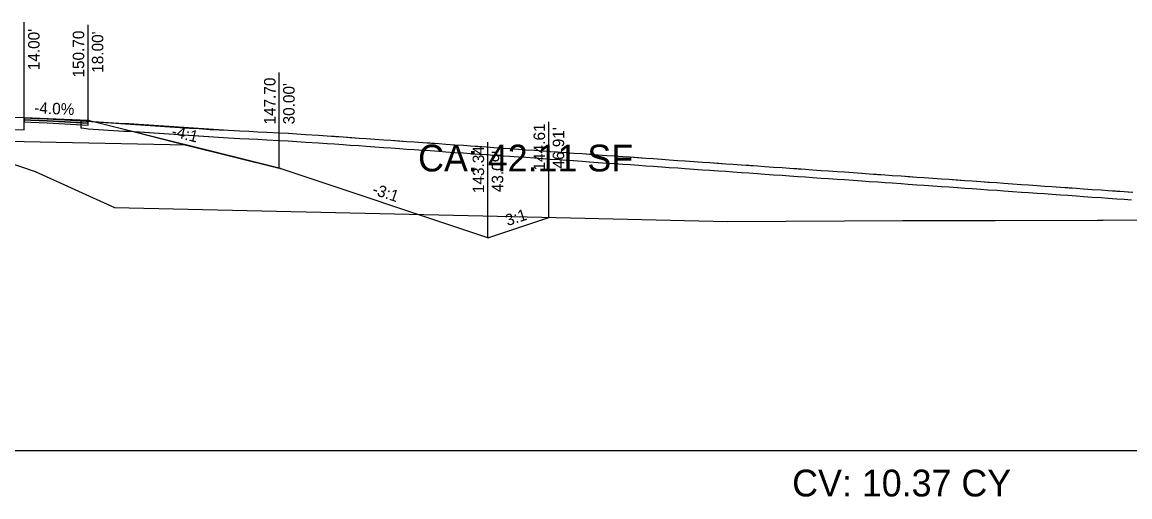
# Model space of a CAD drawing. Extents: x -26 to 4403, y -13 to 9578.
# Drawn here: x 263.9 to 333.4, y 3497.1 to 3526.9 of the extents above; entities that cross this region are included whole.
import ezdxf

# ---------------------------------------------------------------- set-up
doc = ezdxf.new("R2010")
doc.units = 0
for name, color, linetype in [('_CIVIL_CONSTRUCTION', 7, 'Continuous'), ('CONST_DCH', 7, 'Continuous'), ('CONST_LV3', 7, 'Continuous'), ('DTM_CORRIDOR', 7, 'Continuous'), ('DTM_P_FINISHED_GRADE', 7, 'Continuous'), ('DTM_TEMP_DROP', 7, 'Continuous'), ('DTM_X_GROUND', 7, 'Continuous'), ('SLOPE_STAKES_FILL', 7, 'Continuous'), ('XS_CELL', 7, 'Continuous'), ('XS_M_SHAPES_EARTHWORK', 7, 'Continuous'), ('XS_P_ASPHALT', 7, 'Continuous'), ('XS_P_DR_ASPHALT', 7, 'Continuous'), ('XS_P_DR_ASPHALT_B', 7, 'Continuous'), ('XS_P_DR_GRAVEL', 7, 'Continuous'), ('XS_P_GROUND', 7, 'Continuous'), ('XS_P_SHOULDER', 7, 'Continuous'), ('XS_P_SUBGRADE_GRANULAR', 7, 'Continuous'), ('XS_P_TX_CLEARZONE', 7, 'Continuous'), ('XS_P_TX_FS_BS', 7, 'Continuous'), ('XS_SHEET_EW_TX_AREA', 7, 'Continuous'), ('XS_SHEET_EW_TX_VOLUME', 7, 'Continuous')]:
    doc.layers.add(name, color=color, linetype=linetype)

msp = doc.modelspace()

# ---------------------------------------------------------------- linework, layer by layer
at = {"layer": 'CONST_LV3'}
for points in [[(264, 3520.861), (264.203, 3520.853), (264.898, 3520.826), (265.026, 3520.82), (265.203, 3520.813), (265.819, 3520.789), (266.046, 3520.78), (274.373, 3520.208), (274.963, 3520.184), (275.657, 3520.134), (276.23, 3520.111), (276.802, 3520.088), (277.53, 3520.038), (278.089, 3520.016), (278.649, 3519.994), (279.208, 3519.971), (280, 3519.921), (280.55, 3519.899), (281.1, 3519.86), (281.65, 3519.822), (282.453, 3519.776), (283, 3519.737), (283.547, 3519.699), (284, 3519.667), (284.547, 3519.629), (285, 3519.597), (285.453, 3519.566), (286, 3519.527), (286.547, 3519.489), (287, 3519.457), (287.453, 3519.426), (288, 3519.387), (288.453, 3519.356), (289, 3519.317), (289.547, 3519.279), (290, 3519.247), (290.453, 3519.216), (291, 3519.177), (291.547, 3519.139), (292, 3519.107), (292.453, 3519.076), (293, 3519.037), (293.453, 3519.006), (294, 3518.967), (294.453, 3518.936), (295, 3518.897), (295.453, 3518.866), (296, 3518.827), (296.547, 3518.789), (297, 3518.757), (297.453, 3518.726), (298, 3518.687), (298.453, 3518.656), (299, 3518.617), (299.547, 3518.579), (300, 3518.547), (300.547, 3518.509), (301, 3518.477), (301.547, 3518.439), (302, 3518.407), (302.453, 3518.376), (303, 3518.337), (303.453, 3518.306), (304, 3518.267), (304.453, 3518.236), (305, 3518.197), (305.453, 3518.166), (306, 3518.127), (306.547, 3518.089), (307, 3518.057), (307.453, 3518.026), (308, 3517.987), (308.453, 3517.956), (309, 3517.917), (309.547, 3517.879), (310, 3517.847), (310.453, 3517.816), (311, 3517.777), (311.547, 3517.739), (312, 3517.707), (312.453, 3517.676), (313, 3517.637), (313.453, 3517.606), (314, 3517.567), (314.453, 3517.536), (315, 3517.497), (315.453, 3517.466), (316, 3517.427), (316.547, 3517.389), (317, 3517.357), (317.453, 3517.326), (318, 3517.287), (318.453, 3517.256), (319, 3517.217), (319.547, 3517.179), (320, 3517.147), (320.453, 3517.116), (321, 3517.077), (321.547, 3517.039), (322, 3517.007), (322.453, 3516.976), (323, 3516.937), (323.453, 3516.906), (324, 3516.867), (324.547, 3516.829), (325, 3516.797), (325.453, 3516.766), (326, 3516.727), (326.547, 3516.689), (327, 3516.657), (327.547, 3516.619), (328, 3516.587), (328.453, 3516.556), (329, 3516.517), (329.547, 3516.479), (330, 3516.447), (330.453, 3516.416), (331, 3516.377), (331.547, 3516.339), (332, 3516.307), (332.453, 3516.276), (333, 3516.237), (333.547, 3516.199)], [(274.174, 3519.158), (280, 3517.701)]]:
    msp.add_lwpolyline(points, dxfattribs=at)
at = {"layer": 'DTM_P_FINISHED_GRADE'}
for points in [[(264, 3520.861), (264.406, 3520.845), (265.43, 3520.803), (268, 3520.646)], [(267.575, 3520.716), (267.58, 3520.715), (267.583, 3520.715), (267.607, 3520.714), (268, 3520.646), (270.242, 3520.51), (270.562, 3520.497), (276.802, 3520.088), (277.53, 3520.038), (278.089, 3520.016), (278.649, 3519.994), (279.208, 3519.971), (280, 3519.921), (280.55, 3519.899), (281.1, 3519.86), (281.65, 3519.822), (282.453, 3519.776), (283, 3519.737), (283.453, 3519.706), (284, 3519.667), (284.453, 3519.636), (285, 3519.597), (285.453, 3519.566), (286, 3519.527), (286.547, 3519.489), (287, 3519.457), (287.547, 3519.419), (288, 3519.387), (288.453, 3519.356), (289, 3519.317), (289.453, 3519.286), (290, 3519.247), (290.453, 3519.216), (291, 3519.177), (291.547, 3519.139), (292, 3519.107), (292.547, 3519.069), (293, 3519.037), (293.453, 3519.006), (294, 3518.967), (294.453, 3518.936), (295, 3518.897), (295.453, 3518.866), (296, 3518.827), (296.547, 3518.789), (297, 3518.757), (297.547, 3518.719), (298, 3518.687), (298.453, 3518.656), (299, 3518.617), (299.453, 3518.586), (300, 3518.547), (300.547, 3518.509), (301, 3518.477), (301.547, 3518.439), (302, 3518.407), (302.547, 3518.369), (303, 3518.337), (303.453, 3518.306), (304, 3518.267), (304.453, 3518.236), (305, 3518.197), (305.453, 3518.166), (306, 3518.127), (306.547, 3518.089), (307, 3518.057), (307.547, 3518.019), (308, 3517.987), (308.453, 3517.956), (309, 3517.917), (309.453, 3517.886), (310, 3517.847), (310.453, 3517.816), (311, 3517.777), (311.547, 3517.739), (312, 3517.707), (312.547, 3517.669), (313, 3517.637), (313.453, 3517.606), (314, 3517.567), (314.453, 3517.536), (315, 3517.497), (315.453, 3517.466), (316, 3517.427), (316.547, 3517.389), (317, 3517.357), (317.547, 3517.319), (318, 3517.287), (318.453, 3517.256), (319, 3517.217), (319.453, 3517.186), (320, 3517.147), (320.453, 3517.116), (321, 3517.077), (321.547, 3517.039), (322, 3517.007), (322.547, 3516.969), (323, 3516.937), (323.453, 3516.906), (324, 3516.867), (324.453, 3516.836), (325, 3516.797), (325.453, 3516.766), (326, 3516.727), (326.547, 3516.689), (327, 3516.657), (327.547, 3516.619), (328, 3516.587), (328.453, 3516.556), (329, 3516.517), (329.453, 3516.486), (330, 3516.447), (330.453, 3516.416), (331, 3516.377), (331.547, 3516.339), (332, 3516.307), (332.547, 3516.269), (333, 3516.237), (333.453, 3516.206)]]:
    msp.add_lwpolyline(points, dxfattribs=at)
at = {"layer": 'DTM_X_GROUND'}
msp.add_lwpolyline([(255.766, 3520.524), (264.68, 3517.505), (269.665, 3515.248), (296.459, 3514.625), (308.123, 3514.36), (319.103, 3514.434), (324.908, 3514.43), (358.789, 3514.528), (362.204, 3514.527), (383.454, 3514.615), (399.495, 3514.392), (400, 3514.385)], dxfattribs=at)
at = {"layer": 'XS_CELL'}
msp.add_line((250, 3500), (400, 3500), dxfattribs=at)
at = {"layer": 'XS_M_SHAPES_EARTHWORK'}
msp.add_lwpolyline([(333.453, 3515.706), (333, 3515.737), (332.547, 3515.769), (332, 3515.807), (331.547, 3515.839), (331, 3515.877), (330.453, 3515.916), (330, 3515.947), (329.453, 3515.986), (329, 3516.017), (328.453, 3516.056), (328, 3516.087), (327.547, 3516.119), (327, 3516.157), (326.547, 3516.189), (326, 3516.227), (325.453, 3516.266), (325, 3516.297), (324.453, 3516.336), (324, 3516.367), (323.453, 3516.406), (323, 3516.437), (322.547, 3516.469), (322, 3516.507), (321.547, 3516.539), (321, 3516.577), (320.453, 3516.616), (320, 3516.647), (319.453, 3516.686), (319, 3516.717), (318.453, 3516.756), (318, 3516.787), (317.547, 3516.819), (317, 3516.857), (316.547, 3516.889), (316, 3516.927), (315.453, 3516.966), (315, 3516.997), (314.453, 3517.036), (314, 3517.067), (313.453, 3517.106), (313, 3517.137), (312.547, 3517.169), (312, 3517.207), (311.547, 3517.239), (311, 3517.277), (310.453, 3517.316), (310, 3517.347), (309.453, 3517.386), (309, 3517.417), (308.453, 3517.456), (308, 3517.487), (307.547, 3517.519), (307, 3517.557), (306.547, 3517.589), (306, 3517.627), (305.453, 3517.666), (305, 3517.697), (304.453, 3517.736), (304, 3517.767), (303.453, 3517.806), (303, 3517.837), (302.547, 3517.869), (302, 3517.907), (301.547, 3517.939), (301, 3517.977), (300.547, 3518.009), (300, 3518.047), (299.453, 3518.086), (299, 3518.117), (298.453, 3518.156), (298, 3518.187), (297.547, 3518.219), (297, 3518.257), (296.547, 3518.289), (296, 3518.327), (295.453, 3518.366), (295, 3518.397), (294.453, 3518.436), (294, 3518.467), (293.453, 3518.506), (293, 3518.537), (292.547, 3518.569), (292, 3518.607), (291.547, 3518.639), (291, 3518.677), (290.453, 3518.716), (290, 3518.747), (289.453, 3518.786), (289, 3518.817), (288.453, 3518.856), (288, 3518.887), (287.547, 3518.919), (287, 3518.957), (286.547, 3518.989), (286, 3519.027), (285.453, 3519.066), (285, 3519.097), (284.453, 3519.136), (284, 3519.167), (283.453, 3519.206), (283, 3519.237), (282.453, 3519.276), (281.65, 3519.322), (281.1, 3519.36), (280.55, 3519.399), (280, 3519.421), (279.208, 3519.471), (278.649, 3519.494), (278.089, 3519.516), (277.53, 3519.538), (276.802, 3519.588), (270.908, 3519.974), (274.174, 3519.158), (266, 3519.321), (264, 3519.361), (258.897, 3519.464), (264.68, 3517.505), (269.665, 3515.248), (296.459, 3514.625), (308.123, 3514.36), (319.103, 3514.434), (324.908, 3514.43), (350.614, 3514.504)], dxfattribs=at)
at = {"layer": 'XS_P_ASPHALT'}
msp.add_lwpolyline([(250, 3521.141), (236, 3520.861), (236, 3520.861), (236, 3520.111), (250, 3520.391), (250, 3520.391), (250, 3520.391), (264, 3520.111), (264, 3520.861), (264, 3520.861), (250, 3521.141), (250, 3521.141), (250, 3521.141)], dxfattribs=at)
at = {"layer": 'XS_P_DR_ASPHALT'}
msp.add_lwpolyline([(265.43, 3520.803), (264.406, 3520.845), (264, 3520.861), (264, 3520.736), (264.406, 3520.72), (265.43, 3520.678), (268, 3520.521), (268, 3520.646), (265.43, 3520.803)], dxfattribs=at)
at = {"layer": 'XS_P_DR_ASPHALT_B'}
msp.add_lwpolyline([(265.43, 3520.678), (264.406, 3520.72), (264, 3520.736), (264, 3520.611), (264.406, 3520.595), (265.43, 3520.553), (268, 3520.396), (268, 3520.521), (265.43, 3520.678)], dxfattribs=at)
at = {"layer": 'XS_P_DR_GRAVEL'}
for points in [[(333.453, 3515.706), (333, 3515.737), (332.547, 3515.769), (332, 3515.807), (331.547, 3515.839), (331, 3515.877), (330.453, 3515.916), (330, 3515.947), (329.453, 3515.986), (329, 3516.017), (328.453, 3516.056), (328, 3516.087), (327.547, 3516.119), (327, 3516.157), (326.547, 3516.189), (326, 3516.227), (325.453, 3516.266), (325, 3516.297), (324.453, 3516.336), (324, 3516.367), (323.453, 3516.406), (323, 3516.437), (322.547, 3516.469), (322, 3516.507), (321.547, 3516.539), (321, 3516.577), (320.453, 3516.616), (320, 3516.647), (319.453, 3516.686), (319, 3516.717), (318.453, 3516.756), (318, 3516.787), (317.547, 3516.819), (317, 3516.857), (316.547, 3516.889), (316, 3516.927), (315.453, 3516.966), (315, 3516.997), (314.453, 3517.036), (314, 3517.067), (313.453, 3517.106), (313, 3517.137), (312.547, 3517.169), (312, 3517.207), (311.547, 3517.239), (311, 3517.277), (310.453, 3517.316), (310, 3517.347), (309.453, 3517.386), (309, 3517.417), (308.453, 3517.456), (308, 3517.487), (307.547, 3517.519), (307, 3517.557), (306.547, 3517.589), (306, 3517.627), (305.453, 3517.666), (305, 3517.697), (304.453, 3517.736), (304, 3517.767), (303.453, 3517.806), (303, 3517.837), (302.547, 3517.869), (302, 3517.907), (301.547, 3517.939), (301, 3517.977), (300.547, 3518.009), (300, 3518.047), (299.453, 3518.086), (299, 3518.117), (298.453, 3518.156), (298, 3518.187), (297.547, 3518.219), (297, 3518.257), (296.547, 3518.289), (296, 3518.327), (295.453, 3518.366), (295, 3518.397), (294.453, 3518.436), (294, 3518.467), (293.453, 3518.506), (293, 3518.537), (292.547, 3518.569), (292, 3518.607), (291.547, 3518.639), (291, 3518.677), (290.453, 3518.716), (290, 3518.747), (289.453, 3518.786), (289, 3518.817), (288.453, 3518.856), (288, 3518.887), (287.547, 3518.919), (287, 3518.957), (286.547, 3518.989), (286, 3519.027), (285.453, 3519.066), (285, 3519.097), (284.453, 3519.136), (284, 3519.167), (283.453, 3519.206), (283, 3519.237), (282.453, 3519.276), (281.65, 3519.322), (281.1, 3519.36), (280.55, 3519.399), (280, 3519.421), (279.208, 3519.471), (278.649, 3519.494), (278.089, 3519.516), (277.53, 3519.538), (276.802, 3519.588), (270.562, 3519.997), (270.242, 3520.01), (268, 3520.146), (267.607, 3520.214), (267.583, 3520.215), (267.58, 3520.215), (267.575, 3520.216), (267.575, 3520.716), (267.58, 3520.715), (267.583, 3520.715), (267.607, 3520.714), (268, 3520.646), (270.242, 3520.51)], [(270.242, 3520.51), (270.562, 3520.497), (276.802, 3520.088), (277.53, 3520.038), (278.089, 3520.016), (278.649, 3519.994), (279.208, 3519.971), (280, 3519.921), (280.55, 3519.899), (281.1, 3519.86), (281.65, 3519.822), (282.453, 3519.776), (283, 3519.737), (283.453, 3519.706), (284, 3519.667), (284.453, 3519.636), (285, 3519.597), (285.453, 3519.566), (286, 3519.527), (286.547, 3519.489), (287, 3519.457), (287.547, 3519.419), (288, 3519.387), (288.453, 3519.356), (289, 3519.317), (289.453, 3519.286), (290, 3519.247), (290.453, 3519.216), (291, 3519.177), (291.547, 3519.139), (292, 3519.107), (292.547, 3519.069), (293, 3519.037), (293.453, 3519.006), (294, 3518.967), (294.453, 3518.936), (295, 3518.897), (295.453, 3518.866), (296, 3518.827), (296.547, 3518.789), (297, 3518.757), (297.547, 3518.719), (298, 3518.687), (298.453, 3518.656), (299, 3518.617), (299.453, 3518.586), (300, 3518.547), (300.547, 3518.509), (301, 3518.477), (301.547, 3518.439), (302, 3518.407), (302.547, 3518.369), (303, 3518.337), (303.453, 3518.306), (304, 3518.267), (304.453, 3518.236), (305, 3518.197), (305.453, 3518.166), (306, 3518.127), (306.547, 3518.089), (307, 3518.057), (307.547, 3518.019), (308, 3517.987), (308.453, 3517.956), (309, 3517.917), (309.453, 3517.886), (310, 3517.847), (310.453, 3517.816), (311, 3517.777), (311.547, 3517.739), (312, 3517.707), (312.547, 3517.669), (313, 3517.637), (313.453, 3517.606), (314, 3517.567), (314.453, 3517.536), (315, 3517.497), (315.453, 3517.466), (316, 3517.427), (316.547, 3517.389), (317, 3517.357), (317.547, 3517.319), (318, 3517.287), (318.453, 3517.256), (319, 3517.217), (319.453, 3517.186), (320, 3517.147), (320.453, 3517.116), (321, 3517.077), (321.547, 3517.039), (322, 3517.007), (322.547, 3516.969), (323, 3516.937), (323.453, 3516.906), (324, 3516.867), (324.453, 3516.836), (325, 3516.797), (325.453, 3516.766), (326, 3516.727), (326.547, 3516.689), (327, 3516.657), (327.547, 3516.619), (328, 3516.587), (328.453, 3516.556), (329, 3516.517), (329.453, 3516.486), (330, 3516.447), (330.453, 3516.416), (331, 3516.377), (331.547, 3516.339), (332, 3516.307), (332.547, 3516.269), (333, 3516.237), (333.453, 3516.206)]]:
    msp.add_lwpolyline(points, dxfattribs=at)
at = {"layer": 'XS_P_GROUND'}
for points in [[(293.085, 3513.34), (293.085, 3513.34), (280, 3517.701), (268, 3520.701), (268, 3520.701)], [(293.085, 3513.34), (296.909, 3514.615)]]:
    msp.add_lwpolyline(points, dxfattribs=at)
at = {"layer": 'XS_P_SHOULDER'}
msp.add_lwpolyline([(268, 3520.701), (264, 3520.861), (264, 3520.861)], dxfattribs=at)
at = {"layer": 'XS_P_SUBGRADE_GRANULAR'}
for points in [[(264, 3519.361), (250, 3519.641), (250, 3519.641)], [(274.174, 3519.158), (266, 3519.321), (266, 3519.321), (264, 3519.361), (264, 3519.361)]]:
    msp.add_lwpolyline(points, dxfattribs=at)
at = {"layer": 'XS_P_TX_CLEARZONE'}
for p, q in [((264, 3520.861), (264, 3526.861)), ((264, 3520.861), (264, 3526.861)), ((264, 3520.861), (264, 3526.861)), ((264, 3520.861), (264, 3526.861)), ((264, 3520.861), (264, 3526.861)), ((264, 3520.861), (264, 3526.861)), ((268, 3520.701), (268, 3526.701)), ((268, 3520.701), (268, 3526.701)), ((268, 3520.701), (268, 3526.701)), ((268, 3520.701), (268, 3526.701)), ((268, 3520.701), (268, 3526.701)), ((268, 3520.701), (268, 3526.701)), ((280, 3517.701), (280, 3523.701)), ((280, 3517.701), (280, 3523.701)), ((280, 3517.701), (280, 3523.701)), ((280, 3517.701), (280, 3523.701)), ((280, 3517.701), (280, 3523.701)), ((280, 3517.701), (280, 3523.701)), ((296.909, 3514.615), (296.909, 3520.615)), ((296.909, 3514.615), (296.909, 3520.615)), ((296.909, 3514.615), (296.909, 3520.615)), ((296.909, 3514.615), (296.909, 3520.615)), ((296.909, 3514.615), (296.909, 3520.615)), ((296.909, 3514.615), (296.909, 3520.615)), ((293.085, 3513.34), (293.085, 3519.34)), ((293.085, 3513.34), (293.085, 3519.34)), ((293.085, 3513.34), (293.085, 3519.34)), ((293.085, 3513.34), (293.085, 3519.34)), ((293.085, 3513.34), (293.085, 3519.34)), ((293.085, 3513.34), (293.085, 3519.34))]:
    msp.add_line(p, q, dxfattribs=at)

# ---------------------------------------------------------------- texts
at = {"layer": '_CIVIL_CONSTRUCTION'}
msp.add_text('X', height=0.12, dxfattribs=at).set_placement((263.961, 3520.801))
at = {"layer": 'CONST_DCH'}
msp.add_text('X', height=0.12, dxfattribs=at).set_placement((293.046, 3513.28))
at = {"layer": 'DTM_CORRIDOR'}
msp.add_text('X', height=0.12, dxfattribs=at).set_placement((296.87, 3514.555))
at = {"layer": 'DTM_TEMP_DROP'}
msp.add_text('X', height=0.12, dxfattribs=at).set_placement((267.961, 3520.641))
at = {"layer": 'SLOPE_STAKES_FILL'}
msp.add_text('X', height=0.12, dxfattribs=at).set_placement((279.961, 3517.641))
at = {"layer": 'XS_P_TX_CLEARZONE'}
for s, p in [("14.00'", (264.96, 3523.847)), ("14.00'", (264.96, 3523.847)), ("14.00'", (264.96, 3523.847)), ("14.00'", (264.96, 3523.847)), ("14.00'", (264.96, 3523.847)), ("14.00'", (264.96, 3523.847)), ('150.70', (267.76, 3523.387)), ('150.70', (267.76, 3523.387)), ('150.70', (267.76, 3523.387)), ('150.70', (267.76, 3523.387)), ('150.70', (267.76, 3523.387)), ('150.70', (267.76, 3523.387)), ("18.00'", (268.96, 3523.687)), ("18.00'", (268.96, 3523.687)), ("18.00'", (268.96, 3523.687)), ("18.00'", (268.96, 3523.687)), ("18.00'", (268.96, 3523.687)), ("18.00'", (268.96, 3523.687)), ('147.70', (279.76, 3520.443)), ('147.70', (279.76, 3520.443)), ('147.70', (279.76, 3520.443)), ('147.70', (279.76, 3520.443)), ('147.70', (279.76, 3520.443)), ('147.70', (279.76, 3520.443)), ("30.00'", (280.96, 3520.449)), ("30.00'", (280.96, 3520.449)), ("30.00'", (280.96, 3520.449)), ("30.00'", (280.96, 3520.449)), ("30.00'", (280.96, 3520.449)), ("30.00'", (280.96, 3520.449)), ('144.61', (296.669, 3517.566)), ('144.61', (296.669, 3517.566)), ('144.61', (296.669, 3517.566)), ('144.61', (296.669, 3517.566)), ('144.61', (296.669, 3517.566)), ('144.61', (296.669, 3517.566)), ("46.91'", (297.869, 3517.68)), ("46.91'", (297.869, 3517.68)), ("46.91'", (297.869, 3517.68)), ("46.91'", (297.869, 3517.68)), ("46.91'", (297.869, 3517.68)), ("46.91'", (297.869, 3517.68)), ('143.34', (292.845, 3516.144)), ('143.34', (292.845, 3516.144)), ('143.34', (292.845, 3516.144)), ('143.34', (292.845, 3516.144)), ('143.34', (292.845, 3516.144)), ('143.34', (292.845, 3516.144)), ("43.09'", (294.045, 3516.201)), ("43.09'", (294.045, 3516.201)), ("43.09'", (294.045, 3516.201)), ("43.09'", (294.045, 3516.201)), ("43.09'", (294.045, 3516.201)), ("43.09'", (294.045, 3516.201))]:
    msp.add_text(s, height=0.72, rotation=90, dxfattribs=at).set_placement(p)
at = {"layer": 'XS_P_TX_FS_BS'}
for s, rotation, p in [('-4.0%', 357.70939, (264.616, 3521.137)), ('-4.0%', 357.70939, (264.616, 3521.137)), ('-4.0%', 357.70939, (264.616, 3521.137)), ('-4:1', 345.96376, (273.193, 3519.713)), ('-4:1', 345.96376, (273.193, 3519.713)), ('-4:1', 345.96376, (273.193, 3519.713)), ('-3:1', 341.56677, (285.777, 3516.092)), ('-3:1', 341.56677, (285.777, 3516.092)), ('-3:1', 341.56677, (285.777, 3516.092)), ('3:1', 18.43493, (294.321, 3514.069)), ('3:1', 18.43493, (294.321, 3514.069)), ('3:1', 18.43493, (294.321, 3514.069))]:
    msp.add_text(s, height=0.72, rotation=rotation, dxfattribs=at).set_placement(p)
at = {"layer": 'XS_SHEET_EW_TX_AREA'}
msp.add_text('CA: 42.11 SF', height=1.68, dxfattribs=at).set_placement((288.707, 3517.5))
at = {"layer": 'XS_SHEET_EW_TX_VOLUME'}
msp.add_text('CV: 10.37 CY', height=1.68, dxfattribs=at).set_placement((312.171, 3497.12))

doc.saveas('drawing.dxf')
